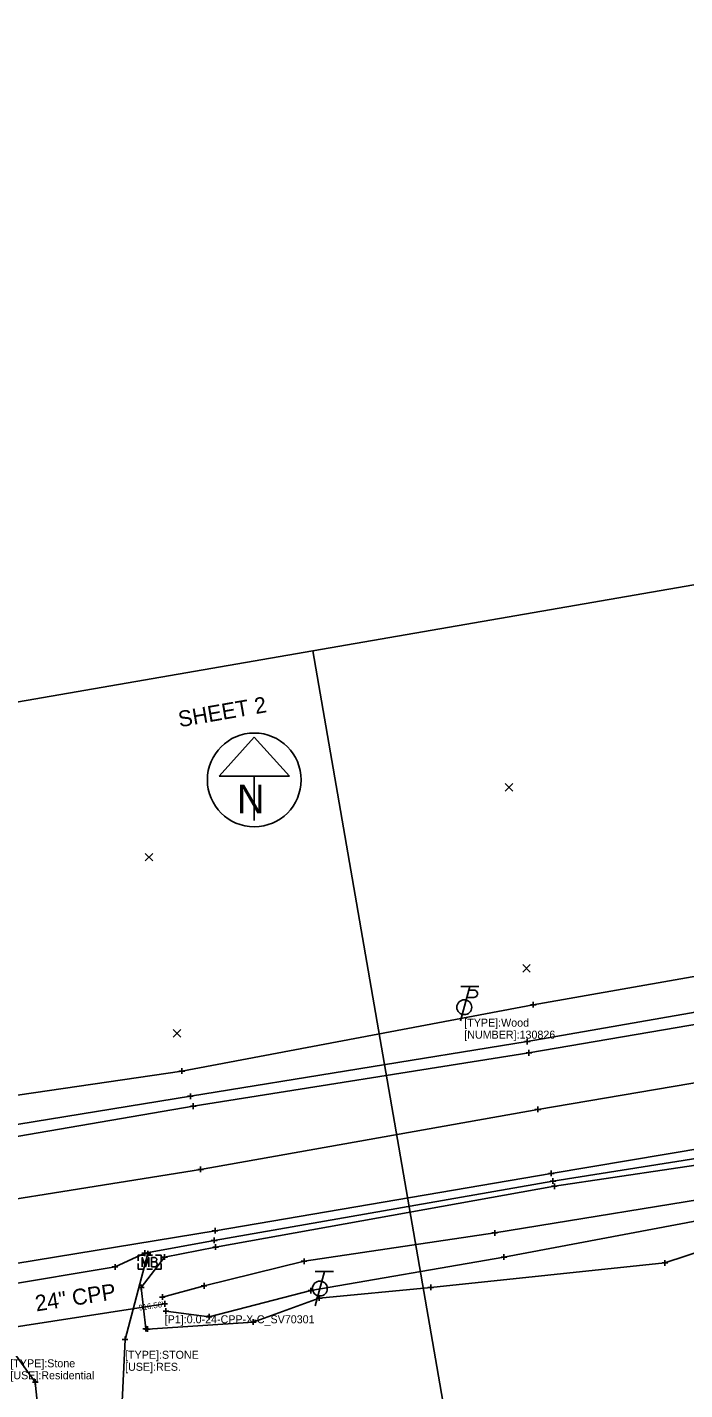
# Model space of a CAD drawing. Extents: x 1386013 to 1389776, y 604170 to 607009.
# Drawn here: x 1386970 to 1387085.1, y 604701.4 to 604939.7 of the extents above; entities that cross this region are included whole.
import ezdxf

# ---------------------------------------------------------------- set-up
doc = ezdxf.new("R2010")
doc.units = 0
for name, color, linetype in [('DR_X_Storm_Sewer', 7, 'Continuous'), ('DR_X_Text', 7, 'Continuous'), ('DV_X_Text', 7, 'Continuous'), ('PM_X_CL_Double_Solid', 7, 'Continuous'), ('PV_X_COP', 7, 'Continuous'), ('PV_X_Driveway', 7, 'Continuous'), ('PV_X_EOP', 7, 'Continuous'), ('PV_X_Shoulder', 7, 'Continuous'), ('RD_X_Cells', 7, 'Continuous'), ('SC_Scratch1', 7, 'Continuous'), ('SH_Cut_Line', 7, 'Continuous'), ('SH_Masking', 7, 'Continuous'), ('SH_Text', 7, 'Continuous'), ('SV_P_Mon_Cells_Set', 7, 'Continuous'), ('SV_X_Random_Point', 7, 'Continuous'), ('SV_X_Text', 7, 'Continuous'), ('SV_X_Toe_of_Slope', 7, 'Continuous'), ('SV_X_Top_of_Bank', 7, 'Continuous'), ('UT_X_Telecom_Cells', 7, 'Continuous')]:
    doc.layers.add(name, color=color, linetype=linetype)

msp = doc.modelspace()

# ---------------------------------------------------------------- linework, layer by layer
at = {"layer": 'DR_X_Storm_Sewer'}
msp.add_line((1386963.45, 604711.66), (1386994.09, 604716.38), dxfattribs=at)
at = {"layer": 'DV_X_Text'}
for p, q in [((1387058.08, 604768.72), (1387059.08, 604768.72)), ((1387058.58, 604769.22), (1387058.58, 604768.22)), ((1387058.58, 604768.72), (1387058.58, 604768.72)), ((1387057.04, 604762.26), (1387058.04, 604762.26)), ((1387057.54, 604762.76), (1387057.54, 604761.76)), ((1387057.54, 604762.26), (1387057.54, 604762.26)), ((1387057.82, 604760.8), (1387057.82, 604759.8)), ((1387057.32, 604760.3), (1387058.32, 604760.3)), ((1387057.82, 604760.3), (1387057.82, 604760.3)), ((1386996.59, 604757.11), (1386997.59, 604757.11)), ((1386997.09, 604757.61), (1386997.09, 604756.61)), ((1386997.09, 604757.11), (1386997.09, 604757.11)), ((1386998.09, 604752.7), (1386999.09, 604752.7)), ((1386998.59, 604753.2), (1386998.59, 604752.2)), ((1386998.59, 604752.7), (1386998.59, 604752.7)), ((1386999.09, 604751.47), (1386999.09, 604750.47)), ((1386998.59, 604750.97), (1386999.59, 604750.97)), ((1386999.09, 604750.97), (1386999.09, 604750.97)), ((1387058.88, 604750.41), (1387059.88, 604750.41)), ((1387059.38, 604750.91), (1387059.38, 604749.91)), ((1387059.38, 604750.41), (1387059.38, 604750.41)), ((1386999.87, 604739.9), (1387000.87, 604739.9)), ((1387000.37, 604740.4), (1387000.37, 604739.4)), ((1387000.37, 604739.9), (1387000.37, 604739.9)), ((1387061.22, 604739.2), (1387062.22, 604739.2)), ((1387061.72, 604739.7), (1387061.72, 604738.7)), ((1387061.72, 604739.2), (1387061.72, 604739.2)), ((1387061.53, 604737.87), (1387062.53, 604737.87)), ((1387061.77, 604736.95), (1387062.77, 604736.95)), ((1387062.03, 604738.37), (1387062.03, 604737.37)), ((1387062.03, 604737.87), (1387062.03, 604737.87)), ((1387062.27, 604737.45), (1387062.27, 604736.45)), ((1387062.27, 604736.95), (1387062.27, 604736.95)), ((1387002.9, 604729.67), (1387002.9, 604728.67)), ((1387002.25, 604727.47), (1387003.25, 604727.47)), ((1387002.4, 604729.17), (1387003.4, 604729.17)), ((1387002.75, 604727.97), (1387002.75, 604726.97)), ((1387002.75, 604727.47), (1387002.75, 604727.47)), ((1387002.9, 604729.17), (1387002.9, 604729.17)), ((1387051.35, 604728.78), (1387052.35, 604728.78)), ((1387051.85, 604729.28), (1387051.85, 604728.28)), ((1387051.85, 604728.78), (1387051.85, 604728.78)), ((1386990.11, 604725.25), (1386991.11, 604725.25)), ((1386990.61, 604725.75), (1386990.61, 604724.75)), ((1386990.61, 604725.25), (1386990.61, 604725.25)), ((1386990.67, 604725.17), (1386991.67, 604725.17)), ((1386991.17, 604725.67), (1386991.17, 604724.67)), ((1386991.17, 604725.17), (1386991.17, 604725.17)), ((1386994.08, 604725.07), (1386994.08, 604724.07)), ((1387002.49, 604726.32), (1387003.49, 604726.32)), ((1387002.99, 604726.82), (1387002.99, 604725.82)), ((1387002.99, 604726.32), (1387002.99, 604726.32)), ((1387053.45, 604725.07), (1387053.45, 604724.07)), ((1386984.9, 604722.84), (1386985.9, 604722.84)), ((1386985.4, 604723.34), (1386985.4, 604722.34)), ((1386985.4, 604722.84), (1386985.4, 604722.84)), ((1386993.58, 604724.57), (1386994.58, 604724.57)), ((1386994.08, 604724.57), (1386994.08, 604724.57)), ((1387017.97, 604723.84), (1387018.97, 604723.84)), ((1387018.47, 604724.34), (1387018.47, 604723.34)), ((1387018.47, 604723.84), (1387018.47, 604723.84)), ((1387052.95, 604724.57), (1387053.95, 604724.57)), ((1387053.45, 604724.57), (1387053.45, 604724.57)), ((1387081.11, 604723.55), (1387082.11, 604723.55)), ((1387081.61, 604724.05), (1387081.61, 604723.05)), ((1387081.61, 604723.55), (1387081.61, 604723.55)), ((1387000.99, 604720.03), (1387000.99, 604719.03)), ((1386989.5, 604719.26), (1386990.5, 604719.26)), ((1386990, 604719.76), (1386990, 604718.76)), ((1386990, 604719.26), (1386990, 604719.26)), ((1386993.7, 604718.06), (1386993.7, 604717.06)), ((1387000.49, 604719.53), (1387001.49, 604719.53)), ((1387000.99, 604719.53), (1387000.99, 604719.53)), ((1387019.19, 604718.71), (1387020.19, 604718.71)), ((1387019.69, 604719.21), (1387019.69, 604718.21)), ((1387019.69, 604718.71), (1387019.69, 604718.71)), ((1387021.12, 604717.88), (1387021.12, 604716.88)), ((1387040.15, 604719.25), (1387041.15, 604719.25)), ((1387040.65, 604719.75), (1387040.65, 604718.75)), ((1387040.65, 604719.25), (1387040.65, 604719.25)), ((1386993.2, 604717.56), (1386994.2, 604717.56)), ((1386993.59, 604716.38), (1386994.59, 604716.38)), ((1386993.7, 604717.56), (1386993.7, 604717.56)), ((1386994.09, 604716.88), (1386994.09, 604715.88)), ((1386994.09, 604716.38), (1386994.09, 604716.38)), ((1386994.32, 604715.6), (1386994.32, 604714.6)), ((1387020.62, 604717.38), (1387021.62, 604717.38)), ((1387021.12, 604717.38), (1387021.12, 604717.38)), ((1386993.82, 604715.1), (1386994.82, 604715.1)), ((1386994.32, 604715.1), (1386994.32, 604715.1)), ((1387001.36, 604714.12), (1387002.36, 604714.12)), ((1387001.86, 604714.62), (1387001.86, 604713.62)), ((1387001.86, 604714.12), (1387001.86, 604714.12)), ((1387009.08, 604713.2), (1387010.08, 604713.2)), ((1387009.58, 604713.7), (1387009.58, 604712.7)), ((1387009.58, 604713.2), (1387009.58, 604713.2)), ((1386987.16, 604710.67), (1386987.16, 604709.67)), ((1386990.27, 604712.03), (1386991.27, 604712.03)), ((1386990.56, 604711.97), (1386991.56, 604711.97)), ((1386990.77, 604712.53), (1386990.77, 604711.53)), ((1386990.77, 604712.03), (1386990.77, 604712.03)), ((1386991.06, 604712.47), (1386991.06, 604711.47)), ((1386991.06, 604711.97), (1386991.06, 604711.97)), ((1386986.66, 604710.17), (1386987.66, 604710.17)), ((1386987.16, 604710.17), (1386987.16, 604710.17)), ((1386970.94, 604702.7), (1386971.94, 604702.7)), ((1386971.44, 604703.2), (1386971.44, 604702.2)), ((1386971.44, 604702.7), (1386971.44, 604702.7))]:
    msp.add_line(p, q, dxfattribs=at)
at = {"layer": 'PM_X_CL_Double_Solid'}
msp.add_lwpolyline([(1386941.92, 604730.57), (1387000.37, 604739.9), (1387059.38, 604750.41), (1387127.32, 604761.93), (1387175.52, 604769.9), (1387233.31, 604779.13), (1387291.85, 604789.88), (1387343.04, 604798.39), (1387403.9, 604809.05), (1387458.49, 604818.93), (1387516.12, 604829.58), (1387574.82, 604839.73), (1387636.99, 604851.11), (1387704.35, 604863.01), (1387787.5, 604877.74), (1387859.73, 604890.76), (1387934.47, 604903.86), (1387998.85, 604914.97), (1388072.27, 604927.44)], dxfattribs=at)
at = {"layer": 'PV_X_COP'}
msp.add_lwpolyline([(1388072.27, 604927.44), (1387998.85, 604914.97), (1387934.47, 604903.86), (1387859.73, 604890.76), (1387787.5, 604877.74), (1387704.35, 604863.01), (1387636.99, 604851.11), (1387574.82, 604839.73), (1387516.12, 604829.58), (1387458.49, 604818.93), (1387403.9, 604809.05), (1387343.04, 604798.39), (1387291.85, 604789.88), (1387233.31, 604779.13), (1387175.52, 604769.9), (1387127.32, 604761.93), (1387059.38, 604750.41), (1387000.37, 604739.9), (1386941.92, 604730.57)], dxfattribs=at)
at = {"layer": 'PV_X_Driveway'}
for points in [[(1386989.09, 604635.22), (1386985.47, 604675.17), (1386987.16, 604710.17), (1386991.17, 604725.17)], [(1386976.17, 604633.16), (1386974.25, 604675.51), (1386971.44, 604702.7), (1386967.09, 604708.68), (1386964.42, 604718.9)]]:
    msp.add_lwpolyline(points, dxfattribs=at)
at = {"layer": 'PV_X_EOP'}
for points in [[(1388070.9, 604937.92), (1387997.67, 604925.46), (1387932.45, 604914.15), (1387857.85, 604900.92), (1387785.1, 604888.09), (1387704.04, 604873.65), (1387634.94, 604861.37), (1387573.23, 604850.33), (1387514.48, 604840.1), (1387457.17, 604829.65), (1387402.44, 604819.9), (1387341.38, 604808.9), (1387290.36, 604800.04), (1387231.98, 604789.91), (1387174.35, 604780.15), (1387125.76, 604771.91), (1387057.82, 604760.3), (1386999.09, 604750.97), (1386941.41, 604741.04)], [(1388073.48, 604916.74), (1388000.2, 604904.18), (1387936.61, 604893.17), (1387861, 604879.89), (1387788.15, 604866.91), (1387706.18, 604852.38), (1387637.62, 604840.16), (1387577.04, 604829.26), (1387518.08, 604818.58), (1387459.96, 604808.24), (1387405.36, 604798.5), (1387345.11, 604787.75), (1387291.8, 604778.43), (1387234.86, 604768.47), (1387177.43, 604758.7), (1387129.4, 604750.56), (1387061.72, 604739.2), (1387002.9, 604729.17), (1386943.42, 604719.4)]]:
    msp.add_lwpolyline(points, dxfattribs=at)
at = {"layer": 'PV_X_Shoulder'}
for points in [[(1388070.88, 604939.75), (1387997.08, 604927.24), (1387932.1, 604916.23), (1387857.34, 604902.99), (1387785.16, 604890.04), (1387703.39, 604875.43), (1387634.35, 604863.66), (1387572.42, 604852.64), (1387514.1, 604842.11), (1387456.78, 604832.26), (1387401.91, 604822.43), (1387340.63, 604811.34), (1387290.11, 604802.67), (1387231.45, 604791.93), (1387174.18, 604782.71), (1387125.33, 604774.1), (1387057.54, 604762.26), (1386998.59, 604752.7), (1386940.97, 604743.32)], [(1388073.66, 604915.38), (1388000.63, 604902.69), (1387936.79, 604891.84), (1387860.98, 604878.42), (1387788.19, 604865.06), (1387706.38, 604850.4), (1387637.88, 604838.5), (1387577.02, 604827.53), (1387518.12, 604817.16), (1387460.26, 604806.85), (1387405.51, 604796.97), (1387345.32, 604786.5), (1387292.14, 604776.93), (1387235.04, 604767.03), (1387177.5, 604757.13), (1387129.28, 604748.59), (1387117.65, 604744.89), (1387099.29, 604741.91), (1387094.7, 604743.05), (1387062.03, 604737.87), (1387002.75, 604727.47), (1386990.61, 604725.25), (1386985.4, 604722.84), (1386965.11, 604719.46)]]:
    msp.add_lwpolyline(points, dxfattribs=at)
at = {"layer": 'RD_X_Cells'}
for p, q in [((1386990.95, 604724.9), (1386991.95, 604724.9)), ((1386990.95, 604722.46), (1386991.95, 604722.46)), ((1386991.46, 604723.68), (1386991.46, 604723.68))]:
    msp.add_line(p, q, dxfattribs=at)
for points in [[(1386989.46, 604723.93), (1386989.46, 604724.9), (1386990.43, 604724.9)], [(1386992.47, 604724.9), (1386993.46, 604724.9), (1386993.46, 604723.93)], [(1386990.43, 604722.46), (1386989.46, 604722.46), (1386989.46, 604723.43)], [(1386990.17, 604722.88), (1386990.17, 604724.48), (1386990.75, 604722.88), (1386991.3, 604724.48), (1386991.3, 604722.88)], [(1386992.48, 604723.75), (1386992.55, 604723.81), (1386992.59, 604723.85), (1386992.61, 604723.89), (1386992.62, 604723.91), (1386992.65, 604723.96), (1386992.66, 604724), (1386992.69, 604724.09), (1386992.69, 604724.13), (1386992.69, 604724.18), (1386992.67, 604724.25), (1386992.65, 604724.32), (1386992.61, 604724.37), (1386992.55, 604724.42), (1386992.5, 604724.44), (1386992.47, 604724.46), (1386992.41, 604724.48), (1386991.79, 604724.48), (1386991.79, 604722.88), (1386992.48, 604722.88), (1386992.57, 604722.93), (1386992.65, 604722.99), (1386992.71, 604723.09), (1386992.75, 604723.21), (1386992.76, 604723.32), (1386992.76, 604723.4), (1386992.74, 604723.47), (1386992.69, 604723.59), (1386992.62, 604723.66), (1386992.48, 604723.75), (1386991.79, 604723.75)], [(1386993.46, 604723.43), (1386993.46, 604722.46), (1386992.47, 604722.46)]]:
    msp.add_lwpolyline(points, dxfattribs=at)
at = {"layer": 'SH_Cut_Line'}
for points in [[(1387057.58, 604613.85), (1387020.03, 604830.63), (1387355.04, 604888.66), (1387392.59, 604671.89)], [(1386722.57, 604555.82), (1386685.02, 604772.59), (1387020.03, 604830.63), (1387057.58, 604613.85)]]:
    msp.add_lwpolyline(points, close=True, dxfattribs=at)
at = {"layer": 'SH_Masking'}
msp.add_circle((1387009.76, 604808.06), 8.2, dxfattribs=at)
at = {"layer": 'SH_Text'}
for p, q in [((1387009.76, 604815.53), (1387003.61, 604808.71)), ((1387015.92, 604808.71), (1387009.76, 604815.53)), ((1387003.61, 604808.71), (1387015.92, 604808.71)), ((1387009.76, 604808.71), (1387009.76, 604800.97))]:
    msp.add_line(p, q, dxfattribs=at)
msp.add_circle((1387009.76, 604808.06), 8.2, dxfattribs=at)
at = {"layer": 'SV_P_Mon_Cells_Set'}
for p, q in [((1387047.48, 604771.88), (1387045.87, 604765.88)), ((1387049.08, 604771.88), (1387045.88, 604771.88)), ((1387047.32, 604771.28), (1387048.17, 604771.28)), ((1387046.97, 604770), (1387048.17, 604770))]:
    msp.add_line(p, q, dxfattribs=at)
msp.add_circle((1387046.51, 604768.28), 1.3, dxfattribs=at)
msp.add_arc((1387048.18, 604770.64), 0.638, 268.8767, 91.1233, dxfattribs=at)
at = {"layer": 'SV_X_Random_Point'}
for p, q in [((1387053.67, 604806.07), (1387055, 604807.41)), ((1387053.67, 604807.41), (1387055, 604806.07)), ((1386990.67, 604793.87), (1386992, 604795.2)), ((1386990.67, 604795.2), (1386992, 604793.87)), ((1387056.73, 604774.41), (1387058.06, 604775.74)), ((1387056.73, 604775.74), (1387058.06, 604774.41)), ((1386995.57, 604763.07), (1386996.9, 604764.4)), ((1386995.57, 604764.4), (1386996.9, 604763.07))]:
    msp.add_line(p, q, dxfattribs=at)
at = {"layer": 'SV_X_Toe_of_Slope'}
for points in [[(1387571.9, 604860.13), (1387513.17, 604847.9), (1387455.73, 604837.69), (1387401.04, 604827.65), (1387339.29, 604815.83), (1387289.1, 604807.74), (1387230.03, 604798.15), (1387173.08, 604787.71), (1387123.84, 604780.19), (1387058.58, 604768.72), (1386997.09, 604757.11), (1386939.93, 604748.73), (1386883.98, 604739), (1386826.09, 604728.82), (1386769.04, 604719.03), (1386711.7, 604710.77), (1386654.03, 604700.72), (1386592.6, 604690.63), (1386534.1, 604681.18), (1386480.03, 604672.89), (1386465.51, 604671.66), (1386391.46, 604656.56), (1386330.8, 604647.36), (1386266.18, 604637.16)], [(1387095.52, 604735.9), (1387051.85, 604728.78), (1387018.47, 604723.84), (1387000.99, 604719.53), (1386993.7, 604717.56)], [(1387096.46, 604732.67), (1387053.45, 604724.57), (1387019.69, 604718.71), (1387001.86, 604714.12), (1386994.32, 604715.1)]]:
    msp.add_lwpolyline(points, dxfattribs=at)
at = {"layer": 'SV_X_Top_of_Bank'}
for points in [[(1387097.14, 604729.59), (1387095.62, 604739.34), (1387092.92, 604741.52), (1387062.27, 604736.95), (1387002.99, 604726.32), (1386994.08, 604724.57), (1386990, 604719.26), (1386990.77, 604712.03)], [(1386991.06, 604711.97), (1387009.58, 604713.2), (1387021.12, 604717.38), (1387040.65, 604719.25), (1387081.61, 604723.55), (1387096.9, 604728.56)]]:
    msp.add_lwpolyline(points, dxfattribs=at)
at = {"layer": 'UT_X_Telecom_Cells'}
for p, q in [((1387022.04, 604722.06), (1387020.43, 604716.06)), ((1387023.64, 604722.06), (1387020.44, 604722.06))]:
    msp.add_line(p, q, dxfattribs=at)
msp.add_circle((1387021.24, 604719.06), 1.3, dxfattribs=at)

# ---------------------------------------------------------------- texts
at = {"layer": 'DR_X_Text'}
msp.add_text('24" CPP', height=2.8, rotation=8.7463, dxfattribs=at).set_placement((1386971.65, 604715.05))
at = {"layer": 'SC_Scratch1'}
msp.add_text("916.56'", height=1, rotation=8.7463, dxfattribs=at).set_placement((1386989.62, 604715.18))
at = {"layer": 'SH_Text'}
msp.add_text('SHEET 2', height=2.8, rotation=9.8279, dxfattribs=at).set_placement((1386996.71, 604817.26))
msp.add_text('N', height=5, dxfattribs=at).set_placement((1387006.74, 604802.23))
at = {"layer": 'SV_X_Text'}
for s, p in [('[TYPE]:Wood', (1387046.51, 604764.88)), ('[NUMBER]:130826', (1387046.51, 604762.78)), ('[P1]:0.0-24-CPP-X-C_SV70301', (1386994.09, 604712.98)), ('[TYPE]:STONE', (1386987.16, 604706.77)), ('[TYPE]:Stone', (1386967.09, 604705.28)), ('[USE]:RES.', (1386987.16, 604704.67)), ('[USE]:Residential', (1386967.09, 604703.18))]:
    msp.add_text(s, height=1.4, dxfattribs=at).set_placement(p)

doc.saveas('drawing.dxf')
